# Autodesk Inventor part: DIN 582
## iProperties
SaveDate: 2002-10-24
SaveTime: 13:49
TotalMass: 0.0 kg
TotalVolume: 0.0 mm^3
Author: Cor de Vlaming
Shininess: 64.0
Angle Display Precision: 2
Document Length Units: 11269
Document Angle Units: 11283
Document Time Units: 11279
Document Mass Units: 11290
Document Length Units Precision: 3
Document Angle Units Precision: 2
Compacted: True
PropertySet Name: _Private Model Information
Created: 2002-10
Part Number: DIN 582
Cost Center: 0.0 kg
Material: C15
Description: Ringmutter
Document SubType Name: Modeling
Designer: Cor de Vlaming
Engineer: Cor de Vlaming
Authority: 0.0 mm^3
Control State: 0
Master: False
Checked Out: False
PropertySet Name: Design Tracking Control
Density: 0.0
Volumn: 0.0
Area: 0.0
PropertySet Name: Model Information
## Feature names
1. Sweep1
2. Revolution1
3. Fillet1
4. Extrusion5
5. Chamfer2
